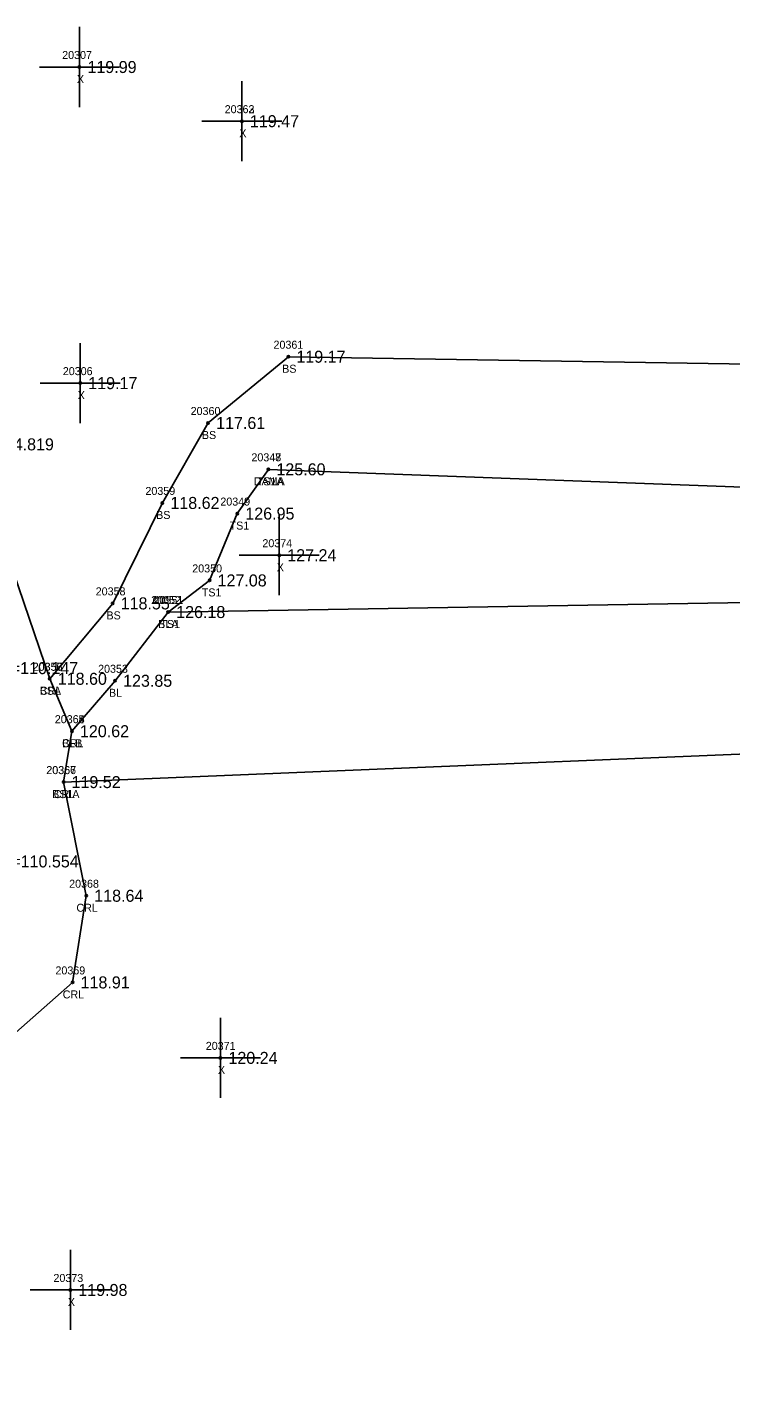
# Model space of a CAD drawing. Extents: x 2375812 to 2377225, y 1024470 to 1025135.
# Drawn here: x 2376550.1 to 2376638, y 1024966.8 to 1025135.2 of the extents above; entities that cross this region are included whole.
import ezdxf

# ---------------------------------------------------------------- set-up
doc = ezdxf.new("R2010")
doc.units = 0
for name, color, linetype in [('RD_DTM_BkLn1', 7, 'Continuous'), ('RD_DTM_BkLn2', 7, 'Continuous'), ('RD_DTM_BkLn_txCode', 7, 'Continuous'), ('RD_EX_Dam', 7, 'Continuous'), ('RD_EX_Dam_txCode', 7, 'Continuous'), ('RD_EX_H2O', 7, 'Continuous'), ('RD_EX_H2O_txCode', 7, 'Continuous'), ('RD_EX_Misc', 7, 'Continuous'), ('RD_EX_Misc_txCode', 7, 'Continuous'), ('RD_EX_TX_Dam_ELEV', 7, 'Continuous'), ('RD_EX_TX_H2O_ELEV', 7, 'Continuous'), ('RD_EX_TX_Misc_ELEV', 7, 'Continuous'), ('RD_SMD_Locator', 7, 'Continuous')]:
    doc.layers.add(name, color=color, linetype=linetype)

msp = doc.modelspace()

# ---------------------------------------------------------------- linework, layer by layer
at = {"layer": 'RD_DTM_BkLn1'}
msp.add_lwpolyline([(2376567.78, 1025062.13), (2376561.15, 1025053.54), (2376555.76, 1025047.24)], dxfattribs=at)
at = {"layer": 'RD_DTM_BkLn2'}
for points in [[(2376552.99, 1025053.79), (2376560.85, 1025063.21), (2376567.06, 1025075.76), (2376572.77, 1025085.75), (2376582.8, 1025094.03), (2376679.85, 1025092.48), (2376779.73, 1025094.91), (2376887.32, 1025089.81), (2376988.9, 1025090.57), (2377106.48, 1025091.22), (2377202.62, 1025093.89)], [(2376580.3, 1025079.96), (2376576.42, 1025074.43), (2376572.95, 1025066.08), (2376567.78, 1025062.13), (2376680.13, 1025064), (2376781.64, 1025064.6), (2376885.5, 1025064.7), (2376986.85, 1025064.56), (2377105.91, 1025065.21), (2377201.99, 1025063.63)], [(2376554.71, 1025040.88), (2376679.34, 1025046.02), (2376781.14, 1025046.61), (2376885.14, 1025046.71), (2376986.57, 1025047.57), (2377105.91, 1025056.21), (2377201.82, 1025050.7)]]:
    msp.add_lwpolyline(points, dxfattribs=at)
at = {"layer": 'RD_EX_Dam'}
msp.add_lwpolyline([(2376580.3, 1025079.96), (2376679.85, 1025076.24), (2376781.56, 1025078.14), (2376886.41, 1025078.13), (2376988.46, 1025077.85), (2377107.1, 1025079.69), (2377202.68, 1025079.96)], dxfattribs=at)
at = {"layer": 'RD_EX_H2O'}
msp.add_lwpolyline([(2376522.68, 1025124.28), (2376539.95, 1025091.93), (2376552.99, 1025053.79), (2376555.76, 1025047.24), (2376554.71, 1025040.88), (2376557.55, 1025026.68), (2376555.84, 1025015.85), (2376539.15, 1025001.14), (2376529.96, 1024972.45), (2376538.09, 1024944), (2376543.21, 1024910.85), (2376536.76, 1024892.22), (2376537.46, 1024874.15), (2376528.94, 1024859.35), (2376567.86, 1024843.78), (2376572.98, 1024831.38), (2376577.78, 1024803.44), (2376559.73, 1024782.76)], dxfattribs=at)
at = {"layer": 'RD_EX_Misc'}
for p, q in [((2376556.7, 1025125.23), (2376556.7, 1025135.23)), ((2376551.7, 1025130.23), (2376561.7, 1025130.23)), ((2376576.99, 1025118.46), (2376576.99, 1025128.46)), ((2376576.99, 1025118.46), (2376576.99, 1025128.46)), ((2376571.99, 1025123.46), (2376581.99, 1025123.46)), ((2376571.99, 1025123.46), (2376581.99, 1025123.46)), ((2376556.8, 1025085.73), (2376556.8, 1025095.73)), ((2376551.8, 1025090.73), (2376561.8, 1025090.73)), ((2376581.66, 1025064.23), (2376581.66, 1025074.23)), ((2376576.66, 1025069.23), (2376586.66, 1025069.23)), ((2376574.31, 1025001.42), (2376574.31, 1025011.42)), ((2376569.31, 1025006.42), (2376579.31, 1025006.42)), ((2376555.56, 1024972.42), (2376555.56, 1024982.42)), ((2376550.56, 1024977.42), (2376560.56, 1024977.42))]:
    msp.add_line(p, q, dxfattribs=at)
at = {"layer": 'RD_SMD_Locator'}
for centre in [(2376556.7, 1025130.23), (2376576.99, 1025123.46), (2376576.99, 1025123.46), (2376582.8, 1025094.03), (2376556.8, 1025090.73), (2376572.77, 1025085.75), (2376580.3, 1025079.96), (2376580.3, 1025079.96), (2376567.06, 1025075.76), (2376576.42, 1025074.43), (2376581.66, 1025069.23), (2376572.95, 1025066.08), (2376560.85, 1025063.21), (2376567.78, 1025062.13), (2376567.78, 1025062.13), (2376552.99, 1025053.79), (2376552.99, 1025053.79), (2376561.15, 1025053.54), (2376555.76, 1025047.24), (2376555.76, 1025047.24), (2376554.71, 1025040.88), (2376554.71, 1025040.88), (2376557.55, 1025026.68), (2376555.84, 1025015.85), (2376574.31, 1025006.42), (2376555.56, 1024977.42)]:
    msp.add_circle(centre, 0.15, dxfattribs=at)

# ---------------------------------------------------------------- texts
at = {"layer": 'RD_DTM_BkLn_txCode'}
for s, p in [('20361', (2376580.94, 1025095.03)), ('BS', (2376582.02, 1025092.03)), ('20360', (2376570.59, 1025086.75)), ('BS', (2376571.99, 1025083.75)), ('20348', (2376578.18, 1025080.96)), ('TS1A', (2376578.85, 1025077.96)), ('20359', (2376564.94, 1025076.76)), ('20349', (2376574.3, 1025075.43)), ('BS', (2376566.28, 1025073.76)), ('TS1', (2376575.46, 1025072.43)), ('20350', (2376570.79, 1025067.08)), ('20358', (2376558.73, 1025064.21)), ('TS1', (2376571.98, 1025064.08)), ('20352', (2376565.66, 1025063.13)), ('20351', (2376565.94, 1025063.13)), ('BS', (2376560.07, 1025061.21)), ('BLA', (2376566.53, 1025060.13)), ('TS1', (2376566.81, 1025060.13)), ('20357', (2376550.87, 1025054.79)), ('20353', (2376559.03, 1025054.54)), ('BSA', (2376551.73, 1025051.79)), ('BL', (2376560.39, 1025051.54)), ('20365', (2376553.62, 1025048.24)), ('BLB', (2376554.53, 1025045.24)), ('20367', (2376552.57, 1025041.88)), ('BS1A', (2376553.28, 1025038.88))]:
    msp.add_text(s, height=1, dxfattribs=at).set_placement(p)
at = {"layer": 'RD_EX_Dam_txCode'}
for s, p in [('20347', (2376578.18, 1025080.96)), ('DAMA', (2376578.48, 1025077.96))]:
    msp.add_text(s, height=1, dxfattribs=at).set_placement(p)
at = {"layer": 'RD_EX_H2O_txCode'}
for s, p in [('20356', (2376550.85, 1025054.79)), ('CRL', (2376551.76, 1025051.79)), ('20364', (2376553.62, 1025048.24)), ('CRL', (2376554.53, 1025045.24)), ('20366', (2376552.55, 1025041.88)), ('CRL', (2376553.48, 1025038.88)), ('20368', (2376555.41, 1025027.68)), ('CRL', (2376556.32, 1025024.68)), ('20369', (2376553.7, 1025016.85)), ('CRL', (2376554.61, 1025013.85))]:
    msp.add_text(s, height=1, dxfattribs=at).set_placement(p)
at = {"layer": 'RD_EX_Misc_txCode'}
for s, p in [('20307', (2376554.54, 1025131.23)), ('X', (2376556.38, 1025128.23)), ('20362', (2376574.84, 1025124.46)), ('20363', (2376574.84, 1025124.46)), ('X', (2376576.67, 1025121.46)), ('X', (2376576.67, 1025121.46)), ('20306', (2376554.62, 1025091.73)), ('X', (2376556.48, 1025088.73)), ('20374', (2376579.55, 1025070.23)), ('X', (2376581.35, 1025067.23)), ('20371', (2376572.48, 1025007.42)), ('X', (2376574, 1025004.42)), ('20373', (2376553.45, 1024978.42)), ('X', (2376555.25, 1024975.42))]:
    msp.add_text(s, height=1, dxfattribs=at).set_placement(p)
at = {"layer": 'RD_EX_TX_Dam_ELEV'}
msp.add_text('125.60', height=1.5, dxfattribs=at).set_placement((2376581.3, 1025079.21))
at = {"layer": 'RD_EX_TX_H2O_ELEV'}
for s, p in [('EL=114.819', (2376542.63, 1025082.33)), ('EL=110.147', (2376545.66, 1025054.37)), ('118.60', (2376553.99, 1025053.04)), ('120.62', (2376556.76, 1025046.49)), ('119.52', (2376555.71, 1025040.13)), ('EL=110.554', (2376545.73, 1025030.22)), ('118.64', (2376558.55, 1025025.93)), ('118.91', (2376556.84, 1025015.1))]:
    msp.add_text(s, height=1.5, dxfattribs=at).set_placement(p)
at = {"layer": 'RD_EX_TX_Misc_ELEV'}
for s, p in [('119.99', (2376557.7, 1025129.48)), ('119.47', (2376577.99, 1025122.71)), ('119.47', (2376577.99, 1025122.71)), ('119.17', (2376583.8, 1025093.28)), ('119.17', (2376557.8, 1025089.98)), ('117.61', (2376573.77, 1025085)), ('125.60', (2376581.3, 1025079.21)), ('118.62', (2376568.06, 1025075.01)), ('126.95', (2376577.42, 1025073.68)), ('127.24', (2376582.66, 1025068.48)), ('127.08', (2376573.95, 1025065.33)), ('118.55', (2376561.85, 1025062.46)), ('126.18', (2376568.78, 1025061.38)), ('126.18', (2376568.78, 1025061.38)), ('118.60', (2376553.99, 1025053.04)), ('123.85', (2376562.15, 1025052.79)), ('120.62', (2376556.76, 1025046.49)), ('119.52', (2376555.71, 1025040.13)), ('120.24', (2376575.31, 1025005.67)), ('119.98', (2376556.56, 1024976.67))]:
    msp.add_text(s, height=1.5, dxfattribs=at).set_placement(p)

doc.saveas('drawing.dxf')
